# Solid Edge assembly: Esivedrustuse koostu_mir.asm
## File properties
Author: Türk
Template: Iso Assembly.asm
Last saved by: Türk
Revision: 15
Application: Solid Edge
Username: Türk
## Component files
Liigend1.par
Polt80x20.par
Mutter.par
Poldikoostu2_mir.asm
si.par
Hoidja_mir.par
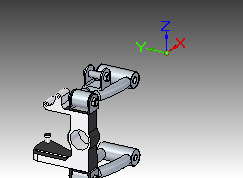
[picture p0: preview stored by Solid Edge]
